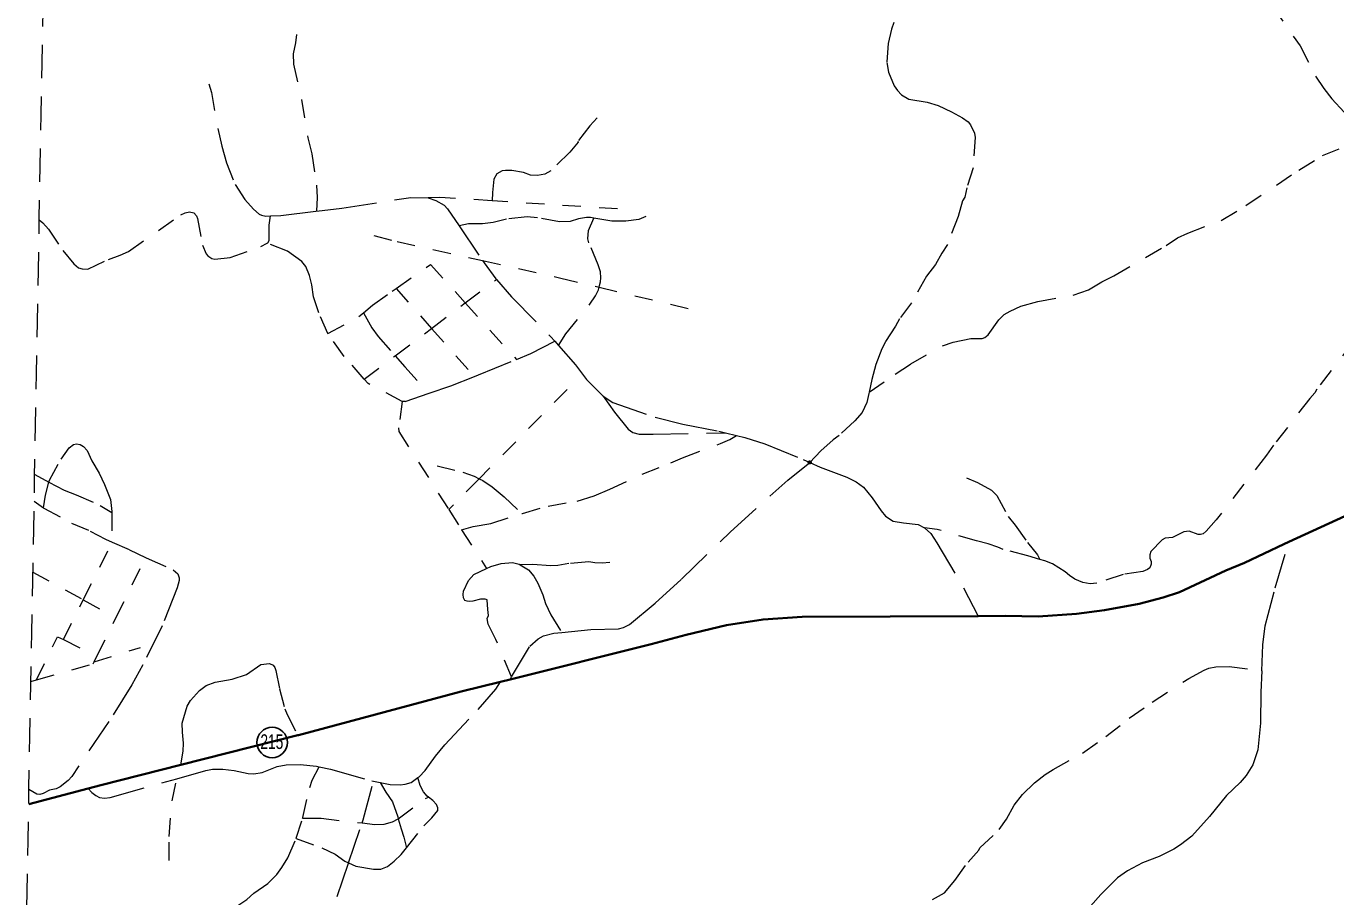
# Model space of a CAD drawing. Extents: x 783.4 to 809.8, y 7536.4 to 7564.6.
# Drawn here: x 783.73 to 790.87, y 7552.69 to 7557.44 of the extents above; entities that cross this region are included whole.
import ezdxf
from ezdxf.enums import TextEntityAlignment as Align

# ---------------------------------------------------------------- set-up
doc = ezdxf.new("R2010")
doc.units = 0
doc.header["$LTSCALE"] = 0.032
doc.header["$PDMODE"] = 32
doc.header["$PDSIZE"] = 0.016
for name, pattern in [('DOTTED', [1.5, 0.3, -1.2]), ('LONG_DASHED', [7.5, 6, -1.5]), ('MEDIUM_DASHED', [4.5, 3, -1.5]), ('SHORT_DASHED', [2.7, 1.5, -1.2])]:
    doc.linetypes.add(name, pattern=pattern)
for name, color, linetype, lineweight in [('13', 7, 'Continuous', 25), ('18', 7, 'DOTTED', 13), ('2', 7, 'Continuous', 35), ('35', 7, 'SHORT_DASHED', 13), ('5', 7, 'LONG_DASHED', 13), ('6', 7, 'MEDIUM_DASHED', 13), ('7', 7, 'DOTTED', 13)]:
    doc.layers.add(name, color=color, linetype=linetype, lineweight=lineweight)
doc.layers.add('61', color=7, linetype='Continuous')

msp = doc.modelspace()

# ---------------------------------------------------------------- linework, layer by layer
at = {"layer": '13'}
msp.add_circle((785.0709, 7553.5342), 0.083, dxfattribs=at)
at = {"layer": '18'}
msp.add_lwpolyline([(790.5277, 7557.551), (790.6798, 7557.3347), (790.764, 7557.1684), (790.8086, 7557.1021), (790.8537, 7557.0458), (791.0331, 7556.8465), (791.0907, 7556.8075), (791.1076, 7556.8025)], dxfattribs=at)
at = {"layer": '2'}
msp.add_line((783.7426, 7553.1976), (784.0673, 7553.2828), dxfattribs=at)
for points in [[(788.9236, 7554.2237), (789.0729, 7554.2243), (789.2498, 7554.221), (789.4603, 7554.2361), (789.6116, 7554.2549), (789.8015, 7554.2901), (789.9318, 7554.324), (790.021, 7554.3531), (790.274, 7554.4729), (790.3763, 7554.5133), (790.5902, 7554.6163), (790.6187, 7554.6293), (791.0992, 7554.8479)], [(786.3687, 7553.8781), (787.1392, 7554.0707), (787.3291, 7554.1219), (787.5506, 7554.1736), (787.7495, 7554.2051), (787.962, 7554.2201), (788.9236, 7554.2237)], [(785.211, 7553.5737), (785.214, 7553.5745), (786.1019, 7553.8114), (786.3173, 7553.8653), (786.3687, 7553.8781)], [(784.0673, 7553.2828), (784.1356, 7553.3007), (784.5734, 7553.4119), (785.211, 7553.5737)]]:
    msp.add_lwpolyline(points, dxfattribs=at)
at = {"layer": '35'}
msp.add_lwpolyline([(783.7288, 7552.4356), (783.7339, 7552.7182), (783.739, 7553.0008), (783.7441, 7553.2834), (783.7492, 7553.566), (783.7543, 7553.8486), (783.7594, 7554.1313), (783.7645, 7554.4139), (783.7696, 7554.6965), (783.7748, 7554.9791), (783.7799, 7555.2617), (783.785, 7555.5443), (783.7901, 7555.8269), (783.7952, 7556.1095), (783.8003, 7556.3921), (783.8054, 7556.6747), (783.8105, 7556.9573), (783.8156, 7557.2399), (783.8207, 7557.5225)], dxfattribs=at)
at = {"layer": '5'}
for p, q in [((785.0369, 7556.4048), (785.062, 7556.406)), ((786.0909, 7556.3518), (786.219, 7556.1626)), ((785.7961, 7555.3933), (785.9272, 7555.4388)), ((787.5449, 7555.2236), (787.6043, 7555.2091)), ((786.3687, 7553.8781), (786.3767, 7553.8915)), ((785.488, 7552.8773), (785.5615, 7553.0953)), ((785.4258, 7552.693), (785.488, 7552.8773))]:
    msp.add_line(p, q, dxfattribs=at)
for points in [[(785.3132, 7556.4319), (785.4504, 7556.4484), (785.8284, 7556.5075), (785.9215, 7556.5049), (785.9227, 7556.5045)], [(785.9227, 7556.5045), (785.9639, 7556.4908), (786.0091, 7556.4651), (786.0276, 7556.4453), (786.0909, 7556.3518)], [(785.062, 7556.406), (785.1191, 7556.4086), (785.3132, 7556.4319)], [(786.219, 7556.1626), (786.2275, 7556.15), (786.2918, 7556.0627), (786.2947, 7556.0594)], [(786.2947, 7556.0594), (786.376, 7555.9658), (786.5896, 7555.7488), (786.6125, 7555.7225), (786.6324, 7555.6998)], [(786.4039, 7555.624), (786.4828, 7555.6567), (786.6125, 7555.7225)], [(786.6324, 7555.6998), (786.7252, 7555.5935), (786.7861, 7555.5133), (786.8766, 7555.4237), (786.8778, 7555.4229)], [(786.1746, 7555.5297), (786.1976, 7555.5386), (786.4039, 7555.624)], [(785.9272, 7555.4388), (786.0467, 7555.4802), (786.1746, 7555.5297)], [(786.8778, 7555.4229), (786.9297, 7555.389), (787.1612, 7555.3082), (787.3111, 7555.2701), (787.5085, 7555.2325), (787.5449, 7555.2236)], [(786.8778, 7555.4229), (786.9386, 7555.3363), (787.0132, 7555.2439), (787.0385, 7555.2252), (787.0731, 7555.2165), (787.149, 7555.2152), (787.5449, 7555.2236)], [(787.6043, 7555.2091), (787.6508, 7555.1977), (787.7595, 7555.1625), (787.969, 7555.0779), (788.004, 7555.062)], [(786.6519, 7554.1344), (786.8106, 7554.15), (786.9612, 7554.1548), (786.9871, 7554.1608), (787.0212, 7554.1775), (787.1607, 7554.2932), (787.3053, 7554.4256), (787.5703, 7554.6813), (787.8838, 7554.9648), (788.004, 7555.062)], [(788.004, 7555.062), (788.0602, 7555.0365), (788.206, 7554.9815), (788.2581, 7554.9562), (788.2972, 7554.9261), (788.3453, 7554.8678), (788.3941, 7554.7971), (788.4181, 7554.768), (788.4592, 7554.7408), (788.5153, 7554.7314), (788.5955, 7554.7229), (788.6296, 7554.705), (788.6306, 7554.7041)], [(788.6306, 7554.7041), (788.6646, 7554.6731), (788.6977, 7554.6233), (788.8435, 7554.3785), (788.9236, 7554.2237)], [(790.4704, 7553.9255), (790.477, 7554.0671), (790.49, 7554.1705), (790.5435, 7554.3778), (790.6187, 7554.6293)], [(784.5526, 7554.3768), (784.4709, 7554.1695), (784.3654, 7553.9578), (784.3052, 7553.8479), (784.179, 7553.6476), (783.9771, 7553.3492), (783.9574, 7553.3274), (783.9142, 7553.293), (783.8918, 7553.281), (783.8567, 7553.2737), (783.8221, 7553.2563), (783.8041, 7553.2507), (783.786, 7553.2516), (783.744, 7553.2779)], [(786.3767, 7553.8915), (786.4762, 7554.0591), (786.523, 7554.0989), (786.5511, 7554.1149), (786.6081, 7554.1301), (786.6519, 7554.1344)], [(790.4704, 7553.9255), (790.4649, 7553.8083), (790.4641, 7553.6403), (790.4491, 7553.4938), (790.4215, 7553.4116), (790.3849, 7553.3538), (790.3521, 7553.3162), (790.2785, 7553.245), (790.1849, 7553.1298), (790.0882, 7553.023), (790.0276, 7552.9755), (789.9915, 7552.952), (789.9103, 7552.9116), (789.8191, 7552.8778), (789.738, 7552.8346), (789.6828, 7552.7961), (789.592, 7552.705), (789.3688, 7552.4514), (789.2016, 7552.2413)], [(785.8658, 7553.3424), (785.8723, 7553.3471), (785.9054, 7553.3819), (785.9625, 7553.4599), (786.0136, 7553.521), (786.1945, 7553.7141), (786.2907, 7553.824), (786.3173, 7553.8653)], [(784.5505, 7553.3365), (784.709, 7553.3811), (784.7462, 7553.3891), (784.8026, 7553.3878), (784.8629, 7553.3808), (784.94, 7553.3654), (784.9707, 7553.3634), (785.0157, 7553.3701), (785.0985, 7553.4022), (785.1467, 7553.4126), (785.2245, 7553.4139), (785.3123, 7553.4045), (785.3275, 7553.4014)], [(785.3275, 7553.4014), (785.3901, 7553.3885), (785.6146, 7553.3246), (785.6241, 7553.3227), (785.66, 7553.3154)], [(784.0673, 7553.2828), (784.0876, 7553.2603), (784.109, 7553.2449), (784.1297, 7553.2348), (784.1554, 7553.2308), (784.1875, 7553.2342), (784.5505, 7553.3365)], [(785.66, 7553.3154), (785.7156, 7553.3041), (785.7691, 7553.303), (785.7971, 7553.3067), (785.8292, 7553.3161), (785.8658, 7553.3424)], [(785.5615, 7553.0953), (785.5669, 7553.1112), (785.6241, 7553.3227)]]:
    msp.add_lwpolyline(points, dxfattribs=at)
at = {"layer": '6'}
for p, q in [((783.7724, 7554.8497), (783.8229, 7554.8132)), ((784.1971, 7554.6276), (784.1987, 7554.6269))]:
    msp.add_line(p, q, dxfattribs=at)
for points in [[(788.4624, 7557.462), (788.4504, 7557.4252), (788.432, 7557.346), (788.424, 7557.2436), (788.4344, 7557.1908), (788.4648, 7557.1156), (788.4824, 7557.09), (788.5056, 7557.0668), (788.5456, 7557.0436), (788.644, 7557.0268), (788.704, 7557.0084), (788.7784, 7556.9748), (788.8368, 7556.942), (788.8688, 7556.9188), (788.8816, 7556.9028), (788.9024, 7556.858), (788.9064, 7556.8348), (788.8952, 7556.6684), (788.8616, 7556.5604), (788.8504, 7556.5084), (788.8376, 7556.4884), (788.8136, 7556.4036), (788.7552, 7556.25), (788.7248, 7556.2027), (788.6912, 7556.1411), (788.6416, 7556.0779), (788.5592, 7555.9315), (788.4936, 7555.8443), (788.4728, 7555.8043), (788.4176, 7555.7203), (788.3976, 7555.6819), (788.364, 7555.5955), (788.3434, 7555.5133), (788.3277, 7555.4449)], [(788.3277, 7555.4449), (788.4697, 7555.544), (788.5555, 7555.5992), (788.7281, 7555.6986), (788.7859, 7555.7185), (788.8833, 7555.7375), (788.9456, 7555.7371), (788.96, 7555.7434), (788.9783, 7555.7579), (789.0362, 7555.8401), (789.0651, 7555.8691), (789.0969, 7555.8871), (789.1567, 7555.9134), (789.2483, 7555.9396), (789.4416, 7555.9744), (789.5254, 7556.0024), (789.5987, 7556.0467), (789.6633, 7556.0801), (789.9491, 7556.2452), (790.0107, 7556.2868), (790.0667, 7556.313), (790.2484, 7556.3812), (790.3843, 7556.4635), (790.6721, 7556.6565), (790.8012, 7556.7351), (790.8928, 7556.7731)], [(783.8002, 7556.3847), (783.8197, 7556.369), (783.8505, 7556.3349), (783.9279, 7556.2176), (783.9895, 7556.145), (784.0147, 7556.124), (784.0343, 7556.117), (784.066, 7556.1153), (784.1771, 7556.1695), (784.2424, 7556.1923), (784.2872, 7556.2124), (784.5723, 7556.4123), (784.5957, 7556.4228), (784.619, 7556.4281), (784.6442, 7556.4237), (784.6582, 7556.4062), (784.6638, 7556.3931), (784.6908, 7556.2461), (784.7104, 7556.1997), (784.7207, 7556.1883), (784.7412, 7556.1743), (784.759, 7556.1708), (784.841, 7556.1788), (785.0087, 7556.24), (785.0443, 7556.258)], [(785.0443, 7556.258), (785.0472, 7556.2595), (785.0547, 7556.2727), (785.0547, 7556.3562), (785.062, 7556.406)], [(786.8266, 7556.3944), (786.8082, 7556.3974), (786.7856, 7556.3974), (786.7428, 7556.3897), (786.6975, 7556.3765), (786.6389, 7556.3737), (786.5187, 7556.3967), (786.4624, 7556.4022), (786.3493, 7556.3886), (786.2759, 7556.3698), (786.2188, 7556.3629), (786.1431, 7556.3629), (786.0909, 7556.3518)], [(787.1092, 7556.4035), (787.072, 7556.3868), (787.001, 7556.3769), (786.9244, 7556.3783), (786.8266, 7556.3944)], [(786.8552, 7556.0174), (786.8575, 7556.0277), (786.862, 7556.0473), (786.8642, 7556.0694), (786.8627, 7556.1007), (786.8501, 7556.1397), (786.7986, 7556.2597), (786.7942, 7556.2819), (786.7964, 7556.3271), (786.8266, 7556.3944)], [(786.6324, 7555.6998), (786.6739, 7555.7635), (786.805, 7555.9251), (786.8345, 7555.9707), (786.8518, 7556.0026), (786.8552, 7556.0174)], [(790.9719, 7555.7223), (790.7713, 7555.4611), (790.7601, 7555.4419), (790.7329, 7555.4107), (790.5352, 7555.1561), (790.4961, 7555.1011), (790.2217, 7554.7483), (790.1681, 7554.6866), (790.1503, 7554.6728), (790.1355, 7554.6679), (790.1237, 7554.6679), (790.0741, 7554.6859), (790.0445, 7554.6825), (789.9831, 7554.6526), (789.9439, 7554.6478), (789.9276, 7554.6388), (789.8658, 7554.5756), (789.8591, 7554.5583), (789.8598, 7554.5388), (789.8665, 7554.5208), (789.8665, 7554.5076), (789.8591, 7554.4875), (789.8465, 7554.4771), (789.8221, 7554.4674), (789.7141, 7554.45), (789.5698, 7554.4036), (789.5347, 7554.3991), (789.494, 7554.406), (789.4511, 7554.4241), (789.4207, 7554.4449), (789.3978, 7554.4657), (789.3282, 7554.508), (789.2876, 7554.524), (789.2603, 7554.5323)], [(788.3277, 7555.4449), (788.3259, 7555.4373), (788.3163, 7555.3881), (788.2904, 7555.3333), (788.2504, 7555.2891), (788.1648, 7555.2091), (788.132, 7555.1851), (788.0648, 7555.1251), (788.004, 7555.062)], [(788.86, 7554.977), (788.9194, 7554.9524), (788.996, 7554.9109), (789.0252, 7554.8816), (789.0866, 7554.7674), (789.1259, 7554.7192), (789.1924, 7554.6257), (789.2478, 7554.5568), (789.2603, 7554.5323)], [(783.8229, 7554.8132), (783.8252, 7554.8115), (783.9763, 7554.7311), (784.0784, 7554.687), (784.1621, 7554.643), (784.1971, 7554.6276)], [(789.2603, 7554.5323), (789.1947, 7554.5521), (789.0592, 7554.5867), (789.0304, 7554.6003), (788.9784, 7554.6171), (788.9136, 7554.6331), (788.6993, 7554.6966), (788.6306, 7554.7041)], [(784.1987, 7554.6269), (784.2928, 7554.5856), (784.3807, 7554.5428)], [(784.3807, 7554.5428), (784.3989, 7554.5339), (784.5316, 7554.4765), (784.5561, 7554.4535), (784.5643, 7554.4325), (784.5643, 7554.4172), (784.5526, 7554.3768)], [(786.3767, 7553.8915), (786.2918, 7554.096), (786.2497, 7554.1786), (786.2441, 7554.2104), (786.251, 7554.2275), (786.2481, 7554.2588), (786.2432, 7554.3119), (786.2326, 7554.3154), (786.2083, 7554.3158), (786.1651, 7554.3056), (786.1475, 7554.3028), (786.1346, 7554.3043), (786.1231, 7554.3088), (786.1157, 7554.3228), (786.1137, 7554.3414), (786.1156, 7554.3597), (786.1422, 7554.4185), (786.171, 7554.4495), (786.2404, 7554.4824)], [(784.5734, 7553.4119), (784.5851, 7553.4861), (784.5878, 7553.5296), (784.5811, 7553.5901), (784.5804, 7553.6395), (784.607, 7553.7326), (784.6248, 7553.7632), (784.6753, 7553.8168), (784.7101, 7553.8446), (784.7591, 7553.8634), (784.8518, 7553.8801), (784.9316, 7553.9055), (785.0087, 7553.9591), (785.0562, 7553.9653), (785.0755, 7553.9556), (785.0851, 7553.9431), (785.0918, 7553.9264), (785.1104, 7553.8269), (785.1408, 7553.717), (785.1519, 7553.6871), (785.211, 7553.5737)], [(788.6736, 7552.6778), (788.7392, 7552.713), (788.796, 7552.781), (788.868, 7552.8818), (788.9264, 7552.9466), (788.932, 7552.9586), (789.0384, 7553.0586), (789.0776, 7553.1154), (789.12, 7553.1914), (789.1656, 7553.2506), (789.2304, 7553.3146), (789.2888, 7553.3594), (789.332, 7553.3874), (789.4928, 7553.4754), (789.6192, 7553.5659), (789.7472, 7553.6659), (789.8721, 7553.7547), (790.0718, 7553.883), (790.1555, 7553.9285), (790.1826, 7553.9398), (790.2198, 7553.9464), (790.293, 7553.9492), (790.4704, 7553.9255)]]:
    msp.add_lwpolyline(points, dxfattribs=at)
msp.add_point((788.004, 7555.062), dxfattribs=at)
at = {"layer": '7'}
for p, q in [((786.9553, 7556.4444), (786.2717, 7556.4886)), ((786.1248, 7555.9316), (786.2947, 7556.0594)), ((785.7468, 7556.0112), (785.9406, 7555.7931)), ((786.8552, 7556.0174), (787.3463, 7555.9002)), ((785.9406, 7555.7931), (786.1248, 7555.9316)), ((786.1248, 7555.9316), (786.4039, 7555.624)), ((785.7416, 7555.6434), (785.9406, 7555.7931)), ((785.9406, 7555.7931), (786.1746, 7555.5297)), ((785.5731, 7555.5166), (785.7416, 7555.6434)), ((786.6808, 7555.4594), (786.2003, 7554.9729)), ((785.7961, 7555.3933), (785.7811, 7555.394)), ((783.7751, 7554.9951), (783.8531, 7554.9542)), ((786.2003, 7554.9729), (786.0343, 7554.8048)), ((786.0343, 7554.8048), (786.1047, 7554.6947)), ((786.1047, 7554.6947), (786.2404, 7554.4824)), ((784.0404, 7554.3119), (784.1987, 7554.6269)), ((783.7654, 7554.4632), (784.0404, 7554.3119)), ((783.9315, 7554.0952), (784.0404, 7554.3119)), ((784.0404, 7554.3119), (784.2182, 7554.2141)), ((784.0996, 7553.9744), (784.3518, 7554.052)), ((784.0996, 7553.9744), (784.1145, 7554.0044)), ((783.7546, 7553.8672), (783.7847, 7553.8757))]:
    msp.add_line(p, q, dxfattribs=at)
for points in [[(785.203, 7557.3951), (785.1979, 7557.3506), (785.1861, 7557.2902), (785.1878, 7557.2345), (785.2318, 7557.0406), (785.2658, 7556.8324), (785.2878, 7556.745), (785.3132, 7556.5733), (785.3166, 7556.5066), (785.3132, 7556.4319)], [(784.7249, 7557.1265), (784.7402, 7557.0804), (784.7741, 7556.8833), (784.7961, 7556.7863), (784.8216, 7556.6957), (784.869, 7556.5781), (784.9216, 7556.4954), (784.9691, 7556.443), (784.9996, 7556.416), (785.0131, 7556.4096), (785.0369, 7556.4048)], [(786.8446, 7556.9414), (786.8037, 7556.8978), (786.7394, 7556.8133), (786.7399, 7556.8092), (786.6951, 7556.754), (786.5919, 7556.6532), (786.5583, 7556.6348), (786.5191, 7556.626), (786.4799, 7556.6292), (786.4423, 7556.6436), (786.3783, 7556.6548), (786.3447, 7556.6548), (786.3263, 7556.6516), (786.2967, 7556.6356), (786.2807, 7556.6076), (786.2727, 7556.5348), (786.2717, 7556.4886)], [(786.2717, 7556.4886), (785.9852, 7556.5071), (785.9227, 7556.5045)], [(785.375, 7555.7654), (785.3252, 7555.8771), (785.2956, 7555.9652), (785.2878, 7556.0296), (785.2752, 7556.0817), (785.2545, 7556.1297), (785.2337, 7556.1576), (785.1551, 7556.2146), (785.0443, 7556.258)], [(785.6248, 7556.2995), (785.7522, 7556.2666), (786.219, 7556.1626)], [(785.7468, 7556.0112), (785.9345, 7556.1413), (786.1248, 7555.9316)], [(786.219, 7556.1626), (786.6392, 7556.069), (786.8552, 7556.0174)], [(785.5691, 7555.8772), (785.6192, 7555.9188), (785.726, 7555.9967), (785.7468, 7556.0112)], [(785.375, 7555.7654), (785.5447, 7555.8569), (785.5691, 7555.8772)], [(785.5691, 7555.8772), (785.6156, 7555.7955), (785.6501, 7555.7485), (785.7416, 7555.6434)], [(785.5731, 7555.5166), (785.4637, 7555.6401), (785.3763, 7555.7624), (785.375, 7555.7654)], [(785.7416, 7555.6434), (785.7948, 7555.5823), (785.9272, 7555.4388)], [(785.7811, 7555.394), (785.5941, 7555.4929), (785.5731, 7555.5166)], [(785.7811, 7555.394), (785.7601, 7555.2498), (785.7615, 7555.2313), (786.0343, 7554.8048)], [(786.4334, 7554.7827), (786.4371, 7554.7839), (786.5769, 7554.8239), (786.7343, 7554.8504), (786.8278, 7554.8803), (786.9131, 7554.9151), (787.09, 7554.9982), (787.2458, 7555.0588), (787.3107, 7555.0875), (787.5174, 7555.1644), (787.5679, 7555.1859), (787.6043, 7555.2091)], [(783.8531, 7554.9542), (783.8559, 7554.9646), (783.9191, 7555.0794), (783.9641, 7555.1407), (783.9865, 7555.1598), (784.0029, 7555.1636), (784.0233, 7555.1598), (784.0416, 7555.1483), (784.0621, 7555.1273), (784.0866, 7555.0698), (784.1274, 7555.0029), (784.156, 7554.9416), (784.1886, 7554.8593), (784.1968, 7554.7942), (784.1968, 7554.7891), (784.1971, 7554.6276)], [(785.9714, 7555.0439), (786.1107, 7555.008), (786.1725, 7554.9876), (786.2003, 7554.9729)], [(786.2003, 7554.9729), (786.2204, 7554.9623), (786.2709, 7554.928), (786.3362, 7554.8741), (786.4334, 7554.7827)], [(783.8229, 7554.8132), (783.8334, 7554.8823), (783.8531, 7554.9542)], [(783.8531, 7554.9542), (783.9355, 7554.911), (784.0023, 7554.8855), (784.1319, 7554.8274), (784.1968, 7554.7891)], [(786.1047, 7554.6947), (786.1668, 7554.7115), (786.264, 7554.7277), (786.4334, 7554.7827)], [(783.9315, 7554.0952), (784.1145, 7554.0044), (784.2182, 7554.2141), (784.3807, 7554.5428)], [(786.2404, 7554.4824), (786.2635, 7554.4934), (786.321, 7554.5103), (786.3816, 7554.5153), (786.4189, 7554.5073), (786.4248, 7554.5036)], [(786.9137, 7554.5164), (786.8719, 7554.5115), (786.8309, 7554.5132), (786.7982, 7554.5188), (786.6899, 7554.5098), (786.6298, 7554.4993), (786.5898, 7554.4972), (786.4937, 7554.5045), (786.4248, 7554.5036)], [(786.4248, 7554.5036), (786.47, 7554.4754), (786.4987, 7554.4415), (786.52, 7554.4026), (786.5476, 7554.3397), (786.5625, 7554.2929), (786.5913, 7554.23), (786.6519, 7554.1344)], [(783.7847, 7553.8757), (783.8997, 7554.111), (783.9315, 7554.0952)], [(783.7847, 7553.8757), (784.0938, 7553.9626), (784.0996, 7553.9744)], [(785.237, 7553.122), (785.238, 7553.1252), (785.2765, 7553.2887), (785.2889, 7553.3283), (785.3275, 7553.4014)], [(784.5087, 7552.8909), (784.5087, 7553.0215), (784.5246, 7553.2149), (784.5505, 7553.3365)], [(785.9244, 7553.2353), (785.9175, 7553.2405), (785.8975, 7553.2641), (785.879, 7553.2995), (785.8658, 7553.3424)], [(785.66, 7553.3154), (785.6906, 7553.2638), (785.7282, 7553.2098), (785.7565, 7553.1283), (785.7591, 7553.1184)], [(785.7591, 7553.1184), (785.9069, 7553.2286), (785.9244, 7553.2353)], [(785.8036, 7552.9589), (785.8986, 7553.0793), (785.943, 7553.123), (785.9741, 7553.1632), (785.9755, 7553.1771), (785.9667, 7553.1958), (785.9478, 7553.2177), (785.9244, 7553.2353)], [(785.2015, 7553.0098), (785.2024, 7553.0118), (785.237, 7553.122)], [(785.237, 7553.122), (785.3379, 7553.1206), (785.5615, 7553.0953)], [(785.5615, 7553.0953), (785.6307, 7553.0875), (785.6812, 7553.0886), (785.7271, 7553.1007), (785.7576, 7553.1173), (785.7591, 7553.1184)], [(785.7591, 7553.1184), (785.7741, 7553.0622), (785.7894, 7553.0181), (785.8036, 7552.9589)], [(784.8732, 7552.6374), (784.9331, 7552.6778), (784.9712, 7552.7112), (785.0475, 7552.7648), (785.0955, 7552.813), (785.1237, 7552.8518), (785.1568, 7552.9054), (785.2015, 7553.0098)], [(785.2015, 7553.0098), (785.3424, 7552.9591), (785.4141, 7552.9249), (785.4669, 7552.8872), (785.488, 7552.8773)], [(785.488, 7552.8773), (785.5273, 7552.8589), (785.6241, 7552.8424), (785.6631, 7552.8436), (785.6995, 7552.8577), (785.7373, 7552.8872), (785.775, 7552.9226), (785.8036, 7552.9589)]]:
    msp.add_lwpolyline(points, dxfattribs=at)

# ---------------------------------------------------------------- texts
at = {"layer": '61', "width": 0.7}
msp.add_text('215', height=0.08, dxfattribs=at).set_placement((785.0692, 7553.4986), align=Align.CENTER)

doc.saveas('drawing.dxf')
